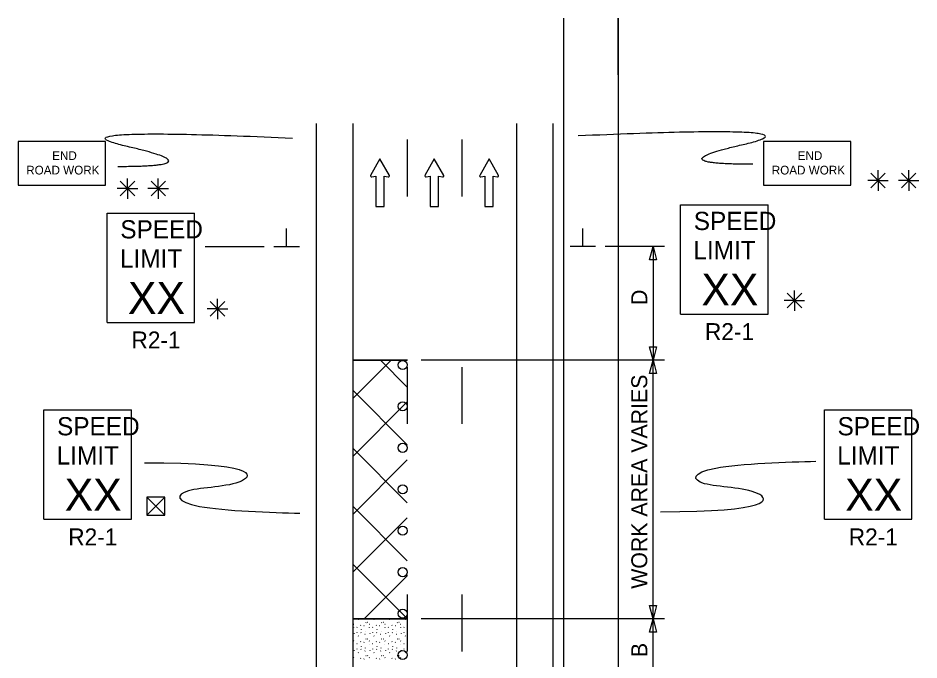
# Model space of a CAD drawing. Extents: x 16724 to 19508, y 5703 to 6974.
# Drawn here: x 16740.8 to 17137, y 6692 to 6974.1 of the extents above; entities that cross this region are included whole.
import ezdxf

# ---------------------------------------------------------------- set-up
doc = ezdxf.new("R2010")
doc.units = 0
for name, color, linetype in [('ALI_LEGAL_EX', 7, 'Continuous'), ('MT_SCRATCH_LEVEL_E', 7, 'Continuous'), ('PAVT_EDGE_EX', 7, 'Continuous'), ('TRAFFIC_SIGNS_PR', 7, 'Continuous'), ('TYPICAL_TEXT_DIMEN_PR', 7, 'Continuous')]:
    doc.layers.add(name, color=color, linetype=linetype)

msp = doc.modelspace()

# ---------------------------------------------------------------- linework, layer by layer
at = {"layer": 'ALI_LEGAL_EX'}
for p, q in [((16980.68, 6974.12), (16980.68, 6155.98)), ((17004.68, 6974.12), (17004.68, 6155.98)), ((16980.68, 6922.21), (16980.68, 6058.3)), ((17004.68, 6922.21), (17004.68, 6058.3))]:
    msp.add_line(p, q, dxfattribs=at)
for points in [[(17004.68, 6949.12), (17004.68, 6974.12)], [(16911.96, 6920.69), (16911.96, 6895.69)], [(16935.96, 6920.69), (16935.96, 6895.69)], [(16911.96, 6820.69), (16911.96, 6795.69)], [(16935.96, 6820.69), (16935.96, 6795.69)], [(16911.96, 6720.69), (16911.96, 6695.69)], [(16935.96, 6720.69), (16935.96, 6695.69)]]:
    msp.add_lwpolyline(points, dxfattribs=at)
at = {"layer": 'MT_SCRATCH_LEVEL_E'}
for p, q in [((16899.96, 6912.2), (16895.85, 6904.96)), ((16904.1, 6904.96), (16899.96, 6912.2)), ((16923.86, 6912.2), (16919.75, 6904.96)), ((16928.01, 6904.96), (16923.86, 6912.2)), ((16947.91, 6912.2), (16943.8, 6904.96)), ((16952.06, 6904.96), (16947.91, 6912.2)), ((16896.33, 6904.28), (16898.1, 6904.59)), ((16898.1, 6904.59), (16898.1, 6891.34)), ((16901.85, 6891.34), (16901.85, 6904.59)), ((16901.85, 6904.59), (16903.62, 6904.28)), ((16920.23, 6904.28), (16922.01, 6904.59)), ((16922.01, 6904.59), (16922.01, 6891.34)), ((16925.75, 6891.34), (16925.75, 6904.59)), ((16925.75, 6904.59), (16927.53, 6904.28)), ((16944.28, 6904.28), (16946.06, 6904.59)), ((16946.06, 6904.59), (16946.06, 6891.34)), ((16949.8, 6891.34), (16949.8, 6904.59)), ((16949.8, 6904.59), (16951.58, 6904.28)), ((16898.1, 6891.34), (16901.85, 6891.34)), ((16922.01, 6891.34), (16925.75, 6891.34)), ((16946.06, 6891.34), (16949.8, 6891.34))]:
    msp.add_line(p, q, dxfattribs=at)
for centre, start, end in [((16896.25, 6904.74), 150.4248, 279.9638), ((16903.69, 6904.74), 260.0362, 29.7731), ((16920.16, 6904.74), 150.4248, 279.9638), ((16927.6, 6904.74), 260.0362, 29.7731), ((16944.21, 6904.74), 150.4248, 279.9638), ((16951.65, 6904.74), 260.0362, 29.7731)]:
    msp.add_arc(centre, 0.463, start, end, dxfattribs=at)
at = {"layer": 'PAVT_EDGE_EX'}
for p, q in [((16871.96, 6927.73), (16871.96, 6180.21)), ((16887.96, 6927.73), (16887.96, 6180.21)), ((16959.96, 6927.73), (16959.96, 6180.21)), ((16975.96, 6927.73), (16975.96, 6180.21)), ((16887.96, 6823.76), (16911.96, 6823.76)), ((16887.96, 6806.86), (16904.85, 6823.76)), ((16912.05, 6823.76), (16888.05, 6823.76)), ((16911.96, 6811.94), (16900.14, 6823.76)), ((16911.96, 6786.49), (16887.96, 6810.49)), ((16887.96, 6781.4), (16911.96, 6805.4)), ((16911.96, 6761.03), (16887.96, 6785.03)), ((16887.96, 6755.95), (16911.96, 6779.95)), ((16911.96, 6735.58), (16887.96, 6759.58)), ((16887.96, 6730.49), (16911.96, 6754.49)), ((16911.96, 6710.12), (16887.96, 6734.12)), ((16892.95, 6710.03), (16912.05, 6729.12)), ((16911.96, 6710.03), (16887.96, 6710.03)), ((16912.05, 6710.03), (16888.05, 6710.03)), ((16888.05, 6710.03), (16912.05, 6710.03)), ((16888.44, 6707.48), (16888.38, 6707.6)), ((16890.46, 6709.68), (16890.4, 6709.79)), ((16893.82, 6708.41), (16893.77, 6708.33)), ((16894.56, 6708.44), (16894.51, 6708.36)), ((16895.32, 6707.48), (16895.27, 6707.6)), ((16897.34, 6709.68), (16897.29, 6709.79)), ((16900.71, 6708.41), (16900.66, 6708.33)), ((16901.45, 6708.44), (16901.4, 6708.36)), ((16902.21, 6707.48), (16902.16, 6707.6)), ((16904.23, 6709.68), (16904.18, 6709.79)), ((16907.6, 6708.41), (16907.55, 6708.33)), ((16908.33, 6708.44), (16908.28, 6708.36)), ((16909.1, 6707.48), (16909.05, 6707.6)), ((16911.12, 6709.68), (16911.07, 6709.79)), ((16912.05, 6710.03), (16912.05, 6710.03)), ((16888.35, 6706.21), (16888.3, 6706.13)), ((16889.84, 6704.14), (16889.78, 6704.07)), ((16889.89, 6706.35), (16889.83, 6706.27)), ((16891.5, 6707.18), (16891.45, 6707.3)), ((16891.63, 6703.89), (16891.58, 6704.01)), ((16891.68, 6705.29), (16891.62, 6705.22)), ((16892.95, 6707.03), (16892.9, 6706.95)), ((16893.6, 6704.42), (16893.55, 6704.54)), ((16895.24, 6706.21), (16895.19, 6706.13)), ((16896.72, 6704.14), (16896.67, 6704.07)), ((16896.77, 6706.35), (16896.72, 6706.27)), ((16898.39, 6707.18), (16898.34, 6707.3)), ((16898.52, 6703.89), (16898.47, 6704.01)), ((16898.56, 6705.29), (16898.51, 6705.22)), ((16899.84, 6707.03), (16899.79, 6706.95)), ((16900.49, 6704.42), (16900.44, 6704.54)), ((16902.13, 6706.21), (16902.08, 6706.13)), ((16903.61, 6704.14), (16903.56, 6704.07)), ((16903.66, 6706.35), (16903.61, 6706.27)), ((16905.28, 6707.18), (16905.23, 6707.3)), ((16905.41, 6703.89), (16905.36, 6704.01)), ((16905.45, 6705.29), (16905.4, 6705.22)), ((16906.73, 6707.03), (16906.68, 6706.95)), ((16907.38, 6704.42), (16907.33, 6704.54)), ((16909.02, 6706.21), (16908.97, 6706.13)), ((16910.5, 6704.14), (16910.45, 6704.07)), ((16910.55, 6706.35), (16910.5, 6706.27)), ((16888.44, 6700.19), (16888.38, 6700.31)), ((16888.56, 6703.57), (16888.54, 6703.45)), ((16890.46, 6702.39), (16890.4, 6702.51)), ((16891.5, 6699.9), (16891.45, 6700.01)), ((16892.95, 6699.74), (16892.9, 6699.67)), ((16893.41, 6703.22), (16893.36, 6703.15)), ((16893.82, 6701.12), (16893.77, 6701.05)), ((16894.56, 6701.15), (16894.51, 6701.08)), ((16895.32, 6700.19), (16895.27, 6700.31)), ((16895.44, 6703.57), (16895.43, 6703.45)), ((16897.34, 6702.39), (16897.29, 6702.51)), ((16898.39, 6699.9), (16898.34, 6700.01)), ((16899.84, 6699.74), (16899.79, 6699.67)), ((16900.3, 6703.22), (16900.25, 6703.15)), ((16900.71, 6701.12), (16900.66, 6701.05)), ((16901.45, 6701.15), (16901.4, 6701.08)), ((16902.21, 6700.19), (16902.16, 6700.31)), ((16902.33, 6703.57), (16902.32, 6703.45)), ((16904.23, 6702.39), (16904.18, 6702.51)), ((16905.28, 6699.9), (16905.23, 6700.01)), ((16906.73, 6699.74), (16906.68, 6699.67)), ((16907.19, 6703.22), (16907.14, 6703.15)), ((16907.6, 6701.12), (16907.55, 6701.05)), ((16908.33, 6701.15), (16908.28, 6701.08)), ((16909.1, 6700.19), (16909.05, 6700.31)), ((16909.22, 6703.57), (16909.21, 6703.45)), ((16911.12, 6702.39), (16911.07, 6702.51)), ((16888.35, 6698.93), (16888.3, 6698.85)), ((16888.56, 6696.28), (16888.54, 6696.16)), ((16889.84, 6696.86), (16889.78, 6696.78)), ((16889.89, 6699.07), (16889.83, 6698.99)), ((16891.63, 6696.61), (16891.58, 6696.72)), ((16891.68, 6698.01), (16891.62, 6697.93)), ((16893.41, 6695.94), (16893.36, 6695.86)), ((16893.6, 6697.14), (16893.55, 6697.25)), ((16895.24, 6698.93), (16895.19, 6698.85)), ((16895.44, 6696.28), (16895.43, 6696.16)), ((16896.72, 6696.86), (16896.67, 6696.78)), ((16896.77, 6699.07), (16896.72, 6698.99)), ((16898.52, 6696.61), (16898.47, 6696.72)), ((16898.56, 6698.01), (16898.51, 6697.93)), ((16900.3, 6695.94), (16900.25, 6695.86)), ((16900.49, 6697.14), (16900.44, 6697.25)), ((16902.13, 6698.93), (16902.08, 6698.85)), ((16902.33, 6696.28), (16902.32, 6696.16)), ((16903.61, 6696.86), (16903.56, 6696.78)), ((16903.66, 6699.07), (16903.61, 6698.99)), ((16905.41, 6696.61), (16905.36, 6696.72)), ((16905.45, 6698.01), (16905.4, 6697.93)), ((16907.19, 6695.94), (16907.14, 6695.86)), ((16907.38, 6697.14), (16907.33, 6697.25)), ((16909.02, 6698.93), (16908.97, 6698.85)), ((16909.22, 6696.28), (16909.21, 6696.16)), ((16910.5, 6696.86), (16910.45, 6696.78)), ((16910.55, 6699.07), (16910.5, 6698.99)), ((16888.44, 6692.91), (16888.38, 6693.03)), ((16890.46, 6695.11), (16890.4, 6695.22)), ((16891.5, 6692.61), (16891.45, 6692.73)), ((16892.95, 6692.46), (16892.9, 6692.38)), ((16893.82, 6693.84), (16893.77, 6693.76)), ((16894.56, 6693.87), (16894.51, 6693.79)), ((16895.32, 6692.91), (16895.27, 6693.03)), ((16897.34, 6695.11), (16897.29, 6695.22)), ((16898.39, 6692.61), (16898.34, 6692.73)), ((16899.84, 6692.46), (16899.79, 6692.38)), ((16900.71, 6693.84), (16900.66, 6693.76)), ((16901.45, 6693.87), (16901.4, 6693.79)), ((16902.21, 6692.91), (16902.16, 6693.03)), ((16904.23, 6695.11), (16904.18, 6695.22)), ((16905.28, 6692.61), (16905.23, 6692.73)), ((16906.73, 6692.46), (16906.68, 6692.38)), ((16907.6, 6693.84), (16907.55, 6693.76)), ((16908.33, 6693.87), (16908.28, 6693.79)), ((16909.1, 6692.91), (16909.05, 6693.03)), ((16911.12, 6695.11), (16911.07, 6695.22))]:
    msp.add_line(p, q, dxfattribs=at)
at = {"layer": 'TRAFFIC_SIGNS_PR'}
for p, q in [((17032.18, 6892.08), (17070.63, 6892.08)), ((17032.18, 6844.02), (17032.18, 6892.08)), ((17070.63, 6844.02), (17070.63, 6892.08)), ((16780, 6888.4), (16818.45, 6888.4)), ((16780, 6840.34), (16780, 6888.4)), ((16818.45, 6840.34), (16818.45, 6888.4)), ((17032.18, 6844.02), (17070.63, 6844.02)), ((16780, 6840.34), (16818.45, 6840.34)), ((16752.19, 6801.84), (16790.64, 6801.84)), ((16752.19, 6753.78), (16752.19, 6801.84)), ((16790.64, 6753.78), (16790.64, 6801.84)), ((17095.41, 6801.84), (17133.86, 6801.84)), ((17095.41, 6753.78), (17095.41, 6801.84)), ((17133.86, 6753.78), (17133.86, 6801.84)), ((16752.19, 6753.78), (16790.64, 6753.78)), ((17095.41, 6753.78), (17133.86, 6753.78))]:
    msp.add_line(p, q, dxfattribs=at)
for points in [[(16740.79, 6900.6), (16779.24, 6900.6), (16779.24, 6919.82), (16740.79, 6919.82)], [(17068.64, 6900.6), (17107.08, 6900.6), (17107.08, 6919.82), (17068.64, 6919.82)]]:
    msp.add_lwpolyline(points, close=True, dxfattribs=at)
for centre in [(16909.95, 6821.64), (16909.95, 6803.42), (16909.95, 6785.21), (16909.95, 6766.99), (16909.95, 6748.78), (16909.95, 6730.56), (16909.95, 6712.35), (16909.95, 6694.14)]:
    msp.add_circle(centre, 2, dxfattribs=at)
for points in [[(16784.71, 6908.91), (16827.22, 6908.91), (16750.7, 6926.32), (16861.49, 6921.38)], [(17063.92, 6909.83), (17021.41, 6909.83), (17097.93, 6927.24), (16987.14, 6922.3)]]:
    msp.add_open_spline(points, degree=2, dxfattribs=at)
at = {"layer": 'TYPICAL_TEXT_DIMEN_PR'}
for p, q in [((17122.16, 6905.91), (17115.78, 6899.53)), ((17115.79, 6905.91), (17122.16, 6899.53)), ((17118.97, 6902.72), (17118.97, 6907.18)), ((17129.29, 6905.91), (17135.67, 6899.53)), ((17135.67, 6905.91), (17129.29, 6899.53)), ((17132.48, 6902.72), (17132.48, 6907.18)), ((16785.78, 6902.36), (16792.15, 6895.99)), ((16792.15, 6902.36), (16785.78, 6895.99)), ((16788.97, 6899.17), (16788.97, 6903.63)), ((16799.28, 6902.36), (16805.66, 6895.99)), ((16805.66, 6902.36), (16799.28, 6895.99)), ((16802.47, 6899.17), (16802.47, 6903.63)), ((17118.97, 6902.72), (17114.44, 6902.72)), ((17118.97, 6902.72), (17122.16, 6902.72)), ((17118.97, 6902.72), (17123.45, 6902.72)), ((17118.97, 6902.72), (17118.97, 6898.22)), ((17132.48, 6902.72), (17127.95, 6902.72)), ((17132.48, 6902.72), (17135.67, 6902.72)), ((17132.48, 6902.72), (17136.96, 6902.72)), ((17132.48, 6902.72), (17132.48, 6898.22)), ((16788.97, 6899.17), (16784.43, 6899.17)), ((16788.97, 6899.17), (16792.15, 6899.17)), ((16788.97, 6899.17), (16793.44, 6899.17)), ((16788.97, 6899.17), (16788.97, 6894.67)), ((16802.47, 6899.17), (16797.94, 6899.17)), ((16802.47, 6899.17), (16805.66, 6899.17)), ((16802.47, 6899.17), (16806.95, 6899.17)), ((16802.47, 6899.17), (16802.47, 6894.67)), ((16858.92, 6873.76), (16858.92, 6881.54)), ((16989.17, 6873.76), (16989.17, 6881.54)), ((16823.05, 6873.76), (16849.05, 6873.76)), ((16853.3, 6873.76), (16864.55, 6873.76)), ((16994.8, 6873.76), (16983.55, 6873.76)), ((17025.05, 6873.76), (16999.05, 6873.76)), ((17018.47, 6867.9), (17020.05, 6873.76)), ((17020.05, 6873.76), (17020.05, 6823.76)), ((17020.05, 6873.76), (17021.62, 6867.9)), ((17020.05, 6867.9), (17018.47, 6867.9)), ((17021.62, 6867.9), (17020.05, 6867.9)), ((17082.22, 6849.97), (17082.22, 6854.42)), ((16828.51, 6846.29), (16828.51, 6850.74)), ((17079.04, 6853.15), (17085.41, 6846.78)), ((17085.41, 6853.15), (17079.04, 6846.78)), ((16828.51, 6846.29), (16823.98, 6846.29)), ((16831.7, 6849.47), (16825.32, 6843.1)), ((16825.33, 6849.47), (16831.7, 6843.1)), ((16828.51, 6846.29), (16831.7, 6846.29)), ((16828.51, 6846.29), (16832.99, 6846.29)), ((16828.51, 6846.29), (16828.51, 6841.79)), ((17082.22, 6849.97), (17077.69, 6849.97)), ((17082.22, 6849.97), (17085.41, 6849.97)), ((17082.22, 6849.97), (17086.7, 6849.97)), ((17082.22, 6849.97), (17082.22, 6845.47)), ((17020.05, 6823.76), (17018.47, 6829.62)), ((17018.47, 6829.62), (17020.05, 6829.62)), ((17020.05, 6829.62), (17021.62, 6829.62)), ((17021.62, 6829.62), (17020.05, 6823.76)), ((17025.05, 6823.76), (16918.04, 6823.76)), ((17018.47, 6817.9), (17020.05, 6823.76)), ((17020.05, 6710.03), (17020.05, 6823.76)), ((17020.05, 6823.76), (17021.62, 6817.9)), ((17020.05, 6817.9), (17018.47, 6817.9)), ((17021.62, 6817.9), (17020.05, 6817.9)), ((16797.39, 6763.56), (16805.39, 6755.56)), ((16797.39, 6755.56), (16805.39, 6763.56)), ((17020.05, 6710.03), (17018.47, 6715.9)), ((17018.47, 6715.9), (17020.05, 6715.9)), ((17020.05, 6715.9), (17021.62, 6715.9)), ((17021.62, 6715.9), (17020.05, 6710.03)), ((17025.05, 6710.03), (16918.04, 6710.03)), ((17018.47, 6704.17), (17020.05, 6710.03)), ((17020.05, 6677.97), (17020.05, 6710.03)), ((17020.05, 6710.03), (17021.62, 6704.17)), ((17020.05, 6704.17), (17018.47, 6704.17)), ((17021.62, 6704.17), (17020.05, 6704.17))]:
    msp.add_line(p, q, dxfattribs=at)
msp.add_lwpolyline([(16797.39, 6763.56), (16797.39, 6755.56), (16805.39, 6755.56), (16805.39, 6763.56)], close=True, dxfattribs=at)
for points, degree in [([(17023.35, 6757.09), (17071.82, 6757.09), (17071.82, 6767.84), (17036.9, 6767.84), (17036.9, 6777.51), (17079.76, 6779.03), (17091.67, 6779.28)], 3), ([(17116.1, 6779.57), (17116.11, 6779.57), (17116.12, 6779.57), (17116.12, 6779.57)], 2), ([(16796.35, 6778.66), (16844.82, 6778.66), (16844.82, 6767.9), (16809.9, 6767.9), (16809.9, 6758.24), (16852.76, 6756.72), (16864.67, 6756.46)], 3)]:
    msp.add_open_spline(points, degree=degree, dxfattribs=at)

# ---------------------------------------------------------------- texts
at = {"layer": 'TRAFFIC_SIGNS_PR'}
for s, height, p in [('END', 3.836, (16755.81, 6911.74)), ('END', 3.836, (17083.65, 6911.74)), ('ROAD WORK', 3.836, (16744.4, 6905.35)), ('ROAD WORK', 3.836, (17072.25, 6905.35)), ('SPEED', 8.01, (17037.95, 6880.93)), ('SPEED', 8.01, (16785.78, 6877.25)), ('LIMIT', 8.01, (17037.79, 6868.11)), ('LIMIT', 8.01, (16785.61, 6864.43)), ('XX', 14.048, (16789.13, 6844.1)), ('XX', 14.048, (17041.3, 6847.78)), ('R2-1', 7.449, (17042.87, 6832.56)), ('R2-1', 7.449, (16790.69, 6828.89)), ('SPEED', 8.01, (16757.96, 6790.69)), ('SPEED', 8.01, (17101.18, 6790.69)), ('LIMIT', 8.01, (16757.8, 6777.87)), ('LIMIT', 8.01, (17101.02, 6777.87)), ('XX', 14.048, (16761.31, 6757.54)), ('XX', 14.048, (17104.53, 6757.54)), ('R2-1', 7.449, (16762.88, 6742.33)), ('R2-1', 7.449, (17106.1, 6742.33))]:
    msp.add_text(s, height=height, dxfattribs=at).set_placement(p)
at = {"layer": 'TYPICAL_TEXT_DIMEN_PR'}
for s, p in [('D', (17017.49, 6847.98)), ('WORK AREA VARIES', (17017.49, 6723.25)), ('B', (17017.49, 6693.24))]:
    msp.add_text(s, height=7, rotation=90, dxfattribs=at).set_placement(p)

doc.saveas('drawing.dxf')
